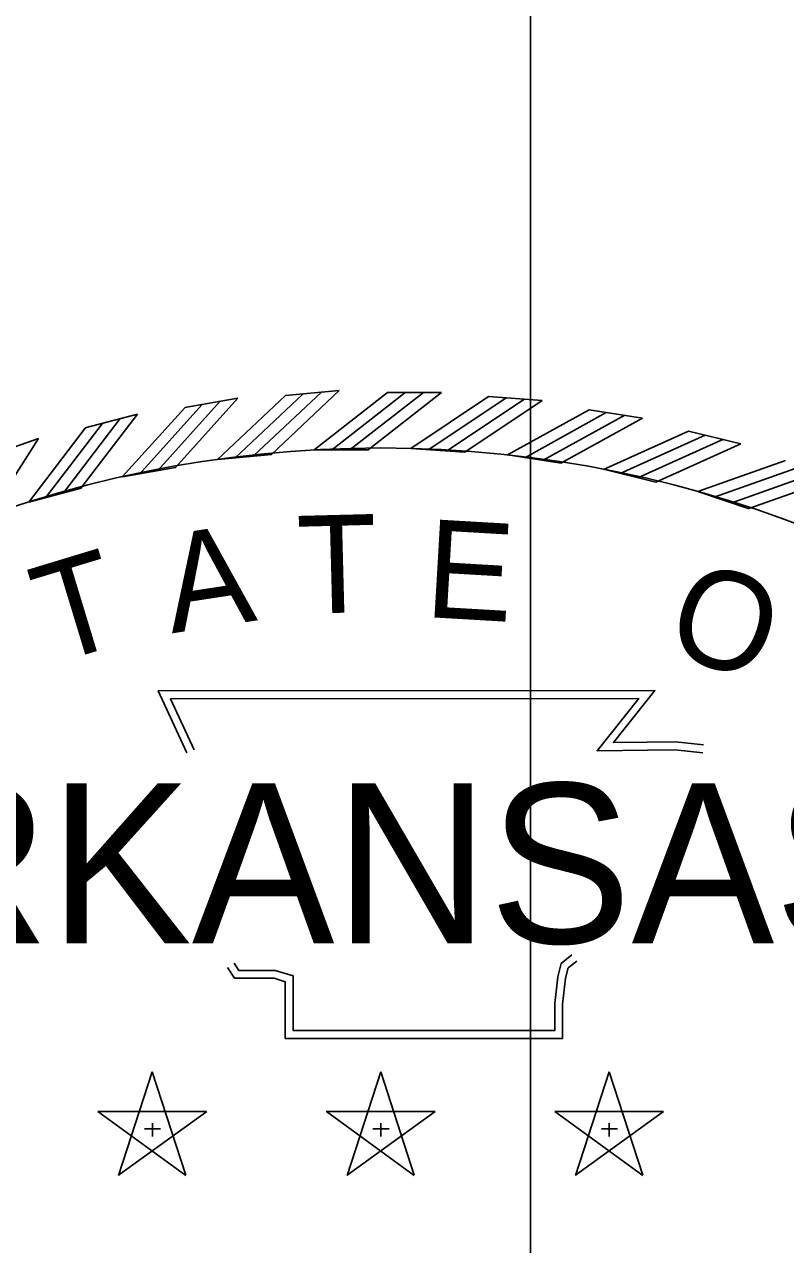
# Model space of a CAD drawing. Extents: x 18 to 14744716, y -5 to 1829144.
# Drawn here: x 17.7415 to 17.7948, y 10.9324 to 11.0178 of the extents above; entities that cross this region are included whole.
import ezdxf

# ---------------------------------------------------------------- set-up
doc = ezdxf.new("R2010")
doc.units = 0
for name, color, linetype in [('B_StampHSS', 7, 'Continuous'), ('B_StampJSB', 7, 'Continuous'), ('B_StampSCR', 7, 'Continuous'), ('B_StampSFH', 7, 'Continuous'), ('R_No Plot', 7, 'Continuous')]:
    doc.layers.add(name, color=color, linetype=linetype)

msp = doc.modelspace()

# ---------------------------------------------------------------- linework, layer by layer
at = {"layer": 'B_StampHSS'}
for p, q in [((17.759782, 10.99184), (17.763536, 10.992186)), ((17.766921, 10.99205), (17.770691, 10.99205)), ((17.752726, 10.990997), (17.756438, 10.991651)), ((17.773983, 10.991767), (17.777742, 10.991491)), ((17.745763, 10.989574), (17.749409, 10.990533)), ((17.78103, 10.990852), (17.784754, 10.990266)), ((17.787978, 10.989358), (17.791641, 10.988467)), ((17.738942, 10.987581), (17.742496, 10.988838)), ((17.755027, 10.987373), (17.75879, 10.98772)), ((17.761776, 10.988038), (17.765555, 10.988038)), ((17.768557, 10.988144), (17.772326, 10.987867)), ((17.775324, 10.987689), (17.779057, 10.987102)), ((17.748356, 10.986153), (17.752077, 10.986809)), ((17.78203, 10.986678), (17.785702, 10.985784)), ((17.741808, 10.984385), (17.745463, 10.985347)), ((17.78863, 10.985115), (17.792215, 10.983921)), ((17.750447, 10.944483), (17.748088, 10.937247)), ((17.752797, 10.937251), (17.750452, 10.944492)), ((17.766438, 10.944483), (17.764079, 10.937247)), ((17.768788, 10.937251), (17.766443, 10.944492)), ((17.782429, 10.944483), (17.78007, 10.937247)), ((17.784779, 10.937251), (17.782434, 10.944492)), ((17.754249, 10.941721), (17.746638, 10.941728)), ((17.746645, 10.941721), (17.752798, 10.937242)), ((17.748097, 10.937251), (17.754258, 10.941719)), ((17.77024, 10.941721), (17.762629, 10.941728)), ((17.762636, 10.941721), (17.768789, 10.937242)), ((17.764088, 10.937251), (17.770249, 10.941719)), ((17.786231, 10.941721), (17.77862, 10.941728)), ((17.778627, 10.941721), (17.78478, 10.937242)), ((17.780079, 10.937251), (17.786241, 10.941719)), ((17.750454, 10.940912), (17.750454, 10.939957)), ((17.766445, 10.940912), (17.766445, 10.939957)), ((17.782436, 10.940912), (17.782436, 10.939957)), ((17.749905, 10.940505), (17.751036, 10.940505)), ((17.765896, 10.940505), (17.767027, 10.940505)), ((17.781887, 10.940505), (17.783018, 10.940505))]:
    msp.add_line(p, q, dxfattribs=at)
for points in [[(17.756232, 10.987469), (17.760986, 10.991936)], [(17.757534, 10.987618), (17.762288, 10.992085)], [(17.758785, 10.987722), (17.763539, 10.992189)], [(17.761772, 10.988035), (17.766915, 10.992046)], [(17.762985, 10.988024), (17.768129, 10.992035)], [(17.764295, 10.988053), (17.769438, 10.992064)], [(17.765551, 10.988041), (17.770694, 10.992053)], [(17.748352, 10.986148), (17.752721, 10.990992)], [(17.749549, 10.986348), (17.753918, 10.991192)], [(17.750833, 10.986604), (17.755202, 10.991448)], [(17.752072, 10.986811), (17.756441, 10.991655)], [(17.755023, 10.987369), (17.759777, 10.991836)], [(17.768553, 10.988141), (17.773977, 10.991764)], [(17.769762, 10.988041), (17.775186, 10.991664)], [(17.77107, 10.987973), (17.776494, 10.991597)], [(17.772322, 10.98787), (17.777746, 10.991493)], [(17.74424, 10.98504), (17.748194, 10.990228)], [(17.745458, 10.985348), (17.749412, 10.990536)], [(17.775319, 10.987687), (17.781024, 10.99085)], [(17.776516, 10.987487), (17.782221, 10.99065)], [(17.777814, 10.987312), (17.783519, 10.990475)], [(17.779053, 10.987105), (17.784758, 10.990268)], [(17.741805, 10.984381), (17.745759, 10.989569)], [(17.742981, 10.984679), (17.746935, 10.989867)], [(17.782025, 10.986675), (17.787972, 10.989356)], [(17.738986, 10.983344), (17.742498, 10.988841)], [(17.783201, 10.986377), (17.789148, 10.989058)], [(17.78448, 10.986096), (17.790427, 10.988777)], [(17.785698, 10.985787), (17.791645, 10.988468)], [(17.788624, 10.985113), (17.794772, 10.987294)], [(17.789772, 10.984719), (17.79592, 10.9869)], [(17.791024, 10.984333), (17.797171, 10.986514)], [(17.792211, 10.983925), (17.798359, 10.986106)], [(17.752875, 10.966818), (17.750865, 10.97117), (17.785635, 10.97119), (17.78273, 10.96754), (17.785092, 10.967571), (17.787065, 10.967597), (17.789037, 10.967382)], [(17.753375, 10.967049), (17.751726, 10.97062), (17.784493, 10.970639), (17.781576, 10.966974), (17.785099, 10.96702), (17.787039, 10.967045), (17.788977, 10.966834)], [(17.779808, 10.952675), (17.779078, 10.95208), (17.778824, 10.951147), (17.778619, 10.949271), (17.778619, 10.947388), (17.760311, 10.947388), (17.760311, 10.950082), (17.760311, 10.951211), (17.759055, 10.951594), (17.756509, 10.951594), (17.756182, 10.952094)], [(17.780156, 10.952247), (17.779563, 10.951765), (17.779366, 10.951044), (17.77917, 10.949241), (17.77917, 10.946838), (17.75976, 10.946838), (17.75976, 10.950082), (17.75976, 10.950803), (17.758973, 10.951044), (17.756212, 10.951044), (17.755721, 10.951792)]]:
    msp.add_lwpolyline(points, dxfattribs=at)
at = {"layer": 'B_StampJSB'}
for p, q in [((17.759782, 10.99184), (17.763536, 10.992186)), ((17.766921, 10.99205), (17.770691, 10.99205)), ((17.752726, 10.990997), (17.756438, 10.991651)), ((17.773983, 10.991767), (17.777742, 10.991491)), ((17.745763, 10.989574), (17.749409, 10.990533)), ((17.78103, 10.990852), (17.784754, 10.990266)), ((17.787978, 10.989358), (17.791641, 10.988467)), ((17.738942, 10.987581), (17.742496, 10.988838)), ((17.755027, 10.987373), (17.75879, 10.98772)), ((17.761776, 10.988038), (17.765555, 10.988038)), ((17.768557, 10.988144), (17.772326, 10.987867)), ((17.775324, 10.987689), (17.779057, 10.987102)), ((17.748356, 10.986153), (17.752077, 10.986809)), ((17.78203, 10.986678), (17.785702, 10.985784)), ((17.741808, 10.984385), (17.745463, 10.985347)), ((17.78863, 10.985115), (17.792215, 10.983921)), ((17.750447, 10.944483), (17.748088, 10.937247)), ((17.752797, 10.937251), (17.750452, 10.944492)), ((17.766438, 10.944483), (17.764079, 10.937247)), ((17.768788, 10.937251), (17.766443, 10.944492)), ((17.782429, 10.944483), (17.78007, 10.937247)), ((17.784779, 10.937251), (17.782434, 10.944492)), ((17.754249, 10.941721), (17.746638, 10.941728)), ((17.746645, 10.941721), (17.752798, 10.937242)), ((17.748097, 10.937251), (17.754258, 10.941719)), ((17.77024, 10.941721), (17.762629, 10.941728)), ((17.762636, 10.941721), (17.768789, 10.937242)), ((17.764088, 10.937251), (17.770249, 10.941719)), ((17.786231, 10.941721), (17.77862, 10.941728)), ((17.778627, 10.941721), (17.78478, 10.937242)), ((17.780079, 10.937251), (17.786241, 10.941719)), ((17.750454, 10.940912), (17.750454, 10.939957)), ((17.766445, 10.940912), (17.766445, 10.939957)), ((17.782436, 10.940912), (17.782436, 10.939957)), ((17.749905, 10.940505), (17.751036, 10.940505)), ((17.765896, 10.940505), (17.767027, 10.940505)), ((17.781887, 10.940505), (17.783018, 10.940505))]:
    msp.add_line(p, q, dxfattribs=at)
for points in [[(17.756232, 10.987469), (17.760986, 10.991936)], [(17.757534, 10.987618), (17.762288, 10.992085)], [(17.758785, 10.987722), (17.763539, 10.992189)], [(17.761772, 10.988035), (17.766915, 10.992046)], [(17.762985, 10.988024), (17.768129, 10.992035)], [(17.764295, 10.988053), (17.769438, 10.992064)], [(17.765551, 10.988041), (17.770694, 10.992053)], [(17.748352, 10.986148), (17.752721, 10.990992)], [(17.749549, 10.986348), (17.753918, 10.991192)], [(17.750833, 10.986604), (17.755202, 10.991448)], [(17.752072, 10.986811), (17.756441, 10.991655)], [(17.755023, 10.987369), (17.759777, 10.991836)], [(17.768553, 10.988141), (17.773977, 10.991764)], [(17.769762, 10.988041), (17.775186, 10.991664)], [(17.77107, 10.987973), (17.776494, 10.991597)], [(17.772322, 10.98787), (17.777746, 10.991493)], [(17.74424, 10.98504), (17.748194, 10.990228)], [(17.745458, 10.985348), (17.749412, 10.990536)], [(17.775319, 10.987687), (17.781024, 10.99085)], [(17.776516, 10.987487), (17.782221, 10.99065)], [(17.777814, 10.987312), (17.783519, 10.990475)], [(17.779053, 10.987105), (17.784758, 10.990268)], [(17.741805, 10.984381), (17.745759, 10.989569)], [(17.742981, 10.984679), (17.746935, 10.989867)], [(17.782025, 10.986675), (17.787972, 10.989356)], [(17.738986, 10.983344), (17.742498, 10.988841)], [(17.783201, 10.986377), (17.789148, 10.989058)], [(17.78448, 10.986096), (17.790427, 10.988777)], [(17.785698, 10.985787), (17.791645, 10.988468)], [(17.788624, 10.985113), (17.794772, 10.987294)], [(17.789772, 10.984719), (17.79592, 10.9869)], [(17.791024, 10.984333), (17.797171, 10.986514)], [(17.792211, 10.983925), (17.798359, 10.986106)], [(17.752875, 10.966818), (17.750865, 10.97117), (17.785635, 10.97119), (17.78273, 10.96754), (17.785092, 10.967571), (17.787065, 10.967597), (17.789037, 10.967382)], [(17.753375, 10.967049), (17.751726, 10.97062), (17.784493, 10.970639), (17.781576, 10.966974), (17.785099, 10.96702), (17.787039, 10.967045), (17.788977, 10.966834)], [(17.779808, 10.952675), (17.779078, 10.95208), (17.778824, 10.951147), (17.778619, 10.949271), (17.778619, 10.947388), (17.760311, 10.947388), (17.760311, 10.950082), (17.760311, 10.951211), (17.759055, 10.951594), (17.756509, 10.951594), (17.756182, 10.952094)], [(17.780156, 10.952247), (17.779563, 10.951765), (17.779366, 10.951044), (17.77917, 10.949241), (17.77917, 10.946838), (17.75976, 10.946838), (17.75976, 10.950082), (17.75976, 10.950803), (17.758973, 10.951044), (17.756212, 10.951044), (17.755721, 10.951792)]]:
    msp.add_lwpolyline(points, dxfattribs=at)
msp.add_circle((17.766447, 10.906117), 0.082054, dxfattribs=at)
at = {"layer": 'B_StampSCR'}
for p, q in [((17.759782, 10.99184), (17.763536, 10.992186)), ((17.766921, 10.99205), (17.770691, 10.99205)), ((17.752726, 10.990997), (17.756438, 10.991651)), ((17.773983, 10.991767), (17.777742, 10.991491)), ((17.745763, 10.989574), (17.749409, 10.990533)), ((17.78103, 10.990852), (17.784754, 10.990266)), ((17.787978, 10.989358), (17.791641, 10.988467)), ((17.738942, 10.987581), (17.742496, 10.988838)), ((17.755027, 10.987373), (17.75879, 10.98772)), ((17.761776, 10.988038), (17.765555, 10.988038)), ((17.768557, 10.988144), (17.772326, 10.987867)), ((17.775324, 10.987689), (17.779057, 10.987102)), ((17.748356, 10.986153), (17.752077, 10.986809)), ((17.78203, 10.986678), (17.785702, 10.985784)), ((17.741808, 10.984385), (17.745463, 10.985347)), ((17.78863, 10.985115), (17.792215, 10.983921)), ((17.750447, 10.944483), (17.748088, 10.937247)), ((17.752797, 10.937251), (17.750452, 10.944492)), ((17.766438, 10.944483), (17.764079, 10.937247)), ((17.768788, 10.937251), (17.766443, 10.944492)), ((17.782429, 10.944483), (17.78007, 10.937247)), ((17.784779, 10.937251), (17.782434, 10.944492)), ((17.754249, 10.941721), (17.746638, 10.941728)), ((17.746645, 10.941721), (17.752798, 10.937242)), ((17.748097, 10.937251), (17.754258, 10.941719)), ((17.77024, 10.941721), (17.762629, 10.941728)), ((17.762636, 10.941721), (17.768789, 10.937242)), ((17.764088, 10.937251), (17.770249, 10.941719)), ((17.786231, 10.941721), (17.77862, 10.941728)), ((17.778627, 10.941721), (17.78478, 10.937242)), ((17.780079, 10.937251), (17.786241, 10.941719)), ((17.750454, 10.940912), (17.750454, 10.939957)), ((17.766445, 10.940912), (17.766445, 10.939957)), ((17.782436, 10.940912), (17.782436, 10.939957)), ((17.749905, 10.940505), (17.751036, 10.940505)), ((17.765896, 10.940505), (17.767027, 10.940505)), ((17.781887, 10.940505), (17.783018, 10.940505))]:
    msp.add_line(p, q, dxfattribs=at)
for points in [[(17.756232, 10.987469), (17.760986, 10.991936)], [(17.757534, 10.987618), (17.762288, 10.992085)], [(17.758785, 10.987722), (17.763539, 10.992189)], [(17.761772, 10.988035), (17.766915, 10.992046)], [(17.762985, 10.988024), (17.768129, 10.992035)], [(17.764295, 10.988053), (17.769438, 10.992064)], [(17.765551, 10.988041), (17.770694, 10.992053)], [(17.748352, 10.986148), (17.752721, 10.990992)], [(17.749549, 10.986348), (17.753918, 10.991192)], [(17.750833, 10.986604), (17.755202, 10.991448)], [(17.752072, 10.986811), (17.756441, 10.991655)], [(17.755023, 10.987369), (17.759777, 10.991836)], [(17.768553, 10.988141), (17.773977, 10.991764)], [(17.769762, 10.988041), (17.775186, 10.991664)], [(17.77107, 10.987973), (17.776494, 10.991597)], [(17.772322, 10.98787), (17.777746, 10.991493)], [(17.74424, 10.98504), (17.748194, 10.990228)], [(17.745458, 10.985348), (17.749412, 10.990536)], [(17.775319, 10.987687), (17.781024, 10.99085)], [(17.776516, 10.987487), (17.782221, 10.99065)], [(17.777814, 10.987312), (17.783519, 10.990475)], [(17.779053, 10.987105), (17.784758, 10.990268)], [(17.741805, 10.984381), (17.745759, 10.989569)], [(17.742981, 10.984679), (17.746935, 10.989867)], [(17.782025, 10.986675), (17.787972, 10.989356)], [(17.738986, 10.983344), (17.742498, 10.988841)], [(17.783201, 10.986377), (17.789148, 10.989058)], [(17.78448, 10.986096), (17.790427, 10.988777)], [(17.785698, 10.985787), (17.791645, 10.988468)], [(17.788624, 10.985113), (17.794772, 10.987294)], [(17.789772, 10.984719), (17.79592, 10.9869)], [(17.791024, 10.984333), (17.797171, 10.986514)], [(17.792211, 10.983925), (17.798359, 10.986106)], [(17.752875, 10.966818), (17.750865, 10.97117), (17.785635, 10.97119), (17.78273, 10.96754), (17.785092, 10.967571), (17.787065, 10.967597), (17.789037, 10.967382)], [(17.753375, 10.967049), (17.751726, 10.97062), (17.784493, 10.970639), (17.781576, 10.966974), (17.785099, 10.96702), (17.787039, 10.967045), (17.788977, 10.966834)], [(17.779808, 10.952675), (17.779078, 10.95208), (17.778824, 10.951147), (17.778619, 10.949271), (17.778619, 10.947388), (17.760311, 10.947388), (17.760311, 10.950082), (17.760311, 10.951211), (17.759055, 10.951594), (17.756509, 10.951594), (17.756182, 10.952094)], [(17.780156, 10.952247), (17.779563, 10.951765), (17.779366, 10.951044), (17.77917, 10.949241), (17.77917, 10.946838), (17.75976, 10.946838), (17.75976, 10.950082), (17.75976, 10.950803), (17.758973, 10.951044), (17.756212, 10.951044), (17.755721, 10.951792)]]:
    msp.add_lwpolyline(points, dxfattribs=at)
at = {"layer": 'B_StampSFH'}
for p, q in [((17.759782, 10.99184), (17.763536, 10.992186)), ((17.766921, 10.99205), (17.770691, 10.99205)), ((17.752726, 10.990997), (17.756438, 10.991651)), ((17.773983, 10.991767), (17.777742, 10.991491)), ((17.745763, 10.989574), (17.749409, 10.990533)), ((17.78103, 10.990852), (17.784754, 10.990266)), ((17.787978, 10.989358), (17.791641, 10.988467)), ((17.738942, 10.987581), (17.742496, 10.988838)), ((17.755027, 10.987373), (17.75879, 10.98772)), ((17.761776, 10.988038), (17.765555, 10.988038)), ((17.768557, 10.988144), (17.772326, 10.987867)), ((17.775324, 10.987689), (17.779057, 10.987102)), ((17.748356, 10.986153), (17.752077, 10.986809)), ((17.78203, 10.986678), (17.785702, 10.985784)), ((17.741808, 10.984385), (17.745463, 10.985347)), ((17.78863, 10.985115), (17.792215, 10.983921)), ((17.750447, 10.944483), (17.748088, 10.937247)), ((17.752797, 10.937251), (17.750452, 10.944492)), ((17.766438, 10.944483), (17.764079, 10.937247)), ((17.768788, 10.937251), (17.766443, 10.944492)), ((17.782429, 10.944483), (17.78007, 10.937247)), ((17.784779, 10.937251), (17.782434, 10.944492)), ((17.754249, 10.941721), (17.746638, 10.941728)), ((17.746645, 10.941721), (17.752798, 10.937242)), ((17.748097, 10.937251), (17.754258, 10.941719)), ((17.77024, 10.941721), (17.762629, 10.941728)), ((17.762636, 10.941721), (17.768789, 10.937242)), ((17.764088, 10.937251), (17.770249, 10.941719)), ((17.786231, 10.941721), (17.77862, 10.941728)), ((17.778627, 10.941721), (17.78478, 10.937242)), ((17.780079, 10.937251), (17.786241, 10.941719)), ((17.750454, 10.940912), (17.750454, 10.939957)), ((17.766445, 10.940912), (17.766445, 10.939957)), ((17.782436, 10.940912), (17.782436, 10.939957)), ((17.749905, 10.940505), (17.751036, 10.940505)), ((17.765896, 10.940505), (17.767027, 10.940505)), ((17.781887, 10.940505), (17.783018, 10.940505))]:
    msp.add_line(p, q, dxfattribs=at)
for points in [[(17.756232, 10.987469), (17.760986, 10.991936)], [(17.757534, 10.987618), (17.762288, 10.992085)], [(17.758785, 10.987722), (17.763539, 10.992189)], [(17.761772, 10.988035), (17.766915, 10.992046)], [(17.762985, 10.988024), (17.768129, 10.992035)], [(17.764295, 10.988053), (17.769438, 10.992064)], [(17.765551, 10.988041), (17.770694, 10.992053)], [(17.748352, 10.986148), (17.752721, 10.990992)], [(17.749549, 10.986348), (17.753918, 10.991192)], [(17.750833, 10.986604), (17.755202, 10.991448)], [(17.752072, 10.986811), (17.756441, 10.991655)], [(17.755023, 10.987369), (17.759777, 10.991836)], [(17.768553, 10.988141), (17.773977, 10.991764)], [(17.769762, 10.988041), (17.775186, 10.991664)], [(17.77107, 10.987973), (17.776494, 10.991597)], [(17.772322, 10.98787), (17.777746, 10.991493)], [(17.74424, 10.98504), (17.748194, 10.990228)], [(17.745458, 10.985348), (17.749412, 10.990536)], [(17.775319, 10.987687), (17.781024, 10.99085)], [(17.776516, 10.987487), (17.782221, 10.99065)], [(17.777814, 10.987312), (17.783519, 10.990475)], [(17.779053, 10.987105), (17.784758, 10.990268)], [(17.741805, 10.984381), (17.745759, 10.989569)], [(17.742981, 10.984679), (17.746935, 10.989867)], [(17.782025, 10.986675), (17.787972, 10.989356)], [(17.738986, 10.983344), (17.742498, 10.988841)], [(17.783201, 10.986377), (17.789148, 10.989058)], [(17.78448, 10.986096), (17.790427, 10.988777)], [(17.785698, 10.985787), (17.791645, 10.988468)], [(17.788624, 10.985113), (17.794772, 10.987294)], [(17.789772, 10.984719), (17.79592, 10.9869)], [(17.791024, 10.984333), (17.797171, 10.986514)], [(17.792211, 10.983925), (17.798359, 10.986106)], [(17.752875, 10.966818), (17.750865, 10.97117), (17.785635, 10.97119), (17.78273, 10.96754), (17.785092, 10.967571), (17.787065, 10.967597), (17.789037, 10.967382)], [(17.753375, 10.967049), (17.751726, 10.97062), (17.784493, 10.970639), (17.781576, 10.966974), (17.785099, 10.96702), (17.787039, 10.967045), (17.788977, 10.966834)], [(17.779808, 10.952675), (17.779078, 10.95208), (17.778824, 10.951147), (17.778619, 10.949271), (17.778619, 10.947388), (17.760311, 10.947388), (17.760311, 10.950082), (17.760311, 10.951211), (17.759055, 10.951594), (17.756509, 10.951594), (17.756182, 10.952094)], [(17.780156, 10.952247), (17.779563, 10.951765), (17.779366, 10.951044), (17.77917, 10.949241), (17.77917, 10.946838), (17.75976, 10.946838), (17.75976, 10.950082), (17.75976, 10.950803), (17.758973, 10.951044), (17.756212, 10.951044), (17.755721, 10.951792)]]:
    msp.add_lwpolyline(points, dxfattribs=at)
at = {"layer": 'R_No Plot'}
msp.add_lwpolyline([(17.776919, 16.627613), (51.776919, 16.627613), (51.776919, -5.372387), (17.776919, -5.372387)], close=True, dxfattribs=at)

# ---------------------------------------------------------------- texts
at = {"layer": 'B_StampHSS'}
for s, rotation, p in [('T', 1.47887, (17.760672, 10.976553)), ('A', 8.67877, (17.751815, 10.975189)), ('E', 356.67203, (17.769449, 10.976345)), ('T', 16.90148, (17.743487, 10.973014)), ('O', 341.2218, (17.786102, 10.973993))]:
    msp.add_text(s, height=0.006859, rotation=rotation, dxfattribs=at).set_placement(p)
msp.add_text('ARKANSAS', height=0.0111938, dxfattribs=at).set_placement((17.722443, 10.953498))
at = {"layer": 'B_StampJSB'}
for s, rotation, p in [('T', 1.47887, (17.760672, 10.976553)), ('A', 8.67877, (17.751815, 10.975189)), ('E', 356.67203, (17.769449, 10.976345)), ('T', 16.90148, (17.743487, 10.973014)), ('O', 341.2218, (17.786102, 10.973993))]:
    msp.add_text(s, height=0.006859, rotation=rotation, dxfattribs=at).set_placement(p)
msp.add_text('ARKANSAS', height=0.0111938, dxfattribs=at).set_placement((17.722443, 10.953498))
at = {"layer": 'B_StampSCR'}
for s, rotation, p in [('T', 1.47887, (17.760672, 10.976553)), ('A', 8.67877, (17.751815, 10.975189)), ('E', 356.67203, (17.769449, 10.976345)), ('T', 16.90148, (17.743487, 10.973014)), ('O', 341.2218, (17.786102, 10.973993))]:
    msp.add_text(s, height=0.006859, rotation=rotation, dxfattribs=at).set_placement(p)
msp.add_text('ARKANSAS', height=0.0111938, dxfattribs=at).set_placement((17.722443, 10.953498))
at = {"layer": 'B_StampSFH'}
for s, rotation, p in [('T', 1.47887, (17.760672, 10.976553)), ('A', 8.67877, (17.751815, 10.975189)), ('E', 356.67203, (17.769449, 10.976345)), ('T', 16.90148, (17.743487, 10.973014)), ('O', 341.2218, (17.786102, 10.973993))]:
    msp.add_text(s, height=0.006859, rotation=rotation, dxfattribs=at).set_placement(p)
msp.add_text('ARKANSAS', height=0.0111938, dxfattribs=at).set_placement((17.722443, 10.953498))

doc.saveas('drawing.dxf')
